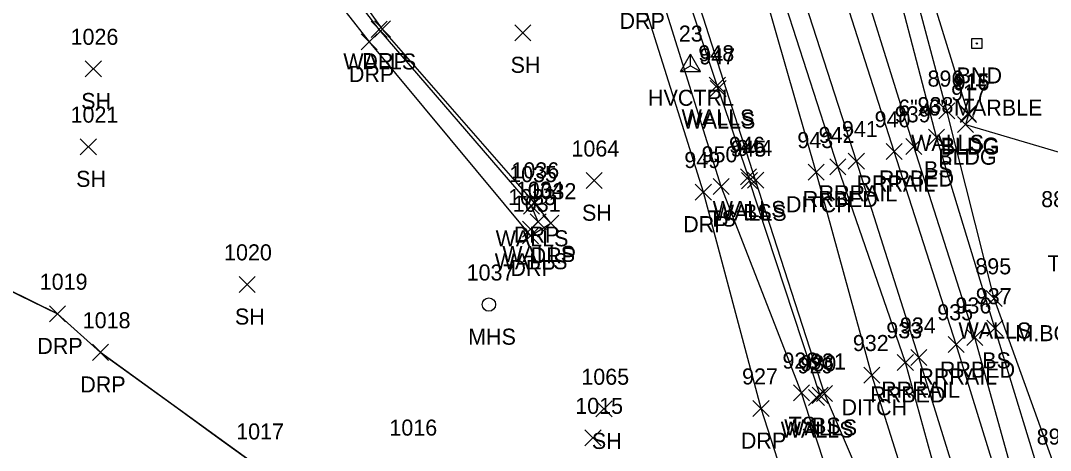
# Model space of a CAD drawing. Extents: x 1462668 to 1465147, y 550359 to 557351.
# Drawn here: x 1464726.3 to 1464854.5, y 552257.6 to 552311.1 of the extents above; entities that cross this region are included whole.
import ezdxf

# ---------------------------------------------------------------- set-up
doc = ezdxf.new("R2010")
doc.units = 0
for name, color, linetype in [('C_A', 7, 'Continuous'), ('C_I', 7, 'Continuous'), ('CPSM', 7, 'Continuous'), ('D_A', 7, 'Continuous'), ('D_I', 7, 'Continuous'), ('D_TIC', 7, 'Continuous'), ('DD', 7, 'Continuous'), ('L_A', 7, 'Continuous'), ('L_C', 7, 'Continuous'), ('L_I', 7, 'Continuous'), ('L_TIC', 7, 'Continuous'), ('LBC', 7, 'Continuous'), ('LELB', 7, 'Continuous'), ('Level 18', 7, 'Continuous'), ('Level 6', 7, 'Continuous'), ('LWS', 7, 'Continuous'), ('M_A', 7, 'Continuous'), ('M_C', 7, 'Continuous'), ('R_A', 7, 'Continuous'), ('R_I', 7, 'Continuous'), ('R_TIC', 7, 'Continuous'), ('RDP', 7, 'Continuous'), ('RR', 7, 'Continuous'), ('RRB', 7, 'Continuous'), ('U_A', 7, 'Continuous'), ('U_I', 7, 'Continuous'), ('USMH', 7, 'Continuous')]:
    doc.layers.add(name, color=color, linetype=linetype)

msp = doc.modelspace()

# ---------------------------------------------------------------- linework, layer by layer
at = {"layer": 'CPSM'}
for p, q in [((1464808.5, 552304.8), (1464809.75, 552306.97)), ((1464811, 552304.8), (1464809.75, 552306.97)), ((1464809.75, 552305.52), (1464809.75, 552306.97)), ((1464808.5, 552304.8), (1464809.75, 552305.52)), ((1464808.5, 552304.8), (1464811, 552304.8)), ((1464809.75, 552305.52), (1464809.75, 552305.52)), ((1464809.75, 552305.52), (1464811, 552304.8))]:
    msp.add_line(p, q, dxfattribs=at)
at = {"layer": 'D_TIC'}
for points in [[(1464824.4, 552291.25), (1464826.4, 552293.25)], [(1464826.4, 552291.25), (1464824.4, 552293.25)], [(1464831.31, 552265.96), (1464833.31, 552267.96)], [(1464833.31, 552265.96), (1464831.31, 552267.96)]]:
    msp.add_lwpolyline(points, dxfattribs=at)
at = {"layer": 'DD'}
msp.add_lwpolyline([(1464838.94, 552245.84), (1464832.31, 552266.96), (1464825.4, 552292.25), (1464817.85, 552318.61), (1464804.29, 552354.78), (1464798.74, 552370.92), (1464794.98, 552381.16)], dxfattribs=at)
at = {"layer": 'L_TIC'}
for points in [[(1464769.98, 552309.05), (1464771.98, 552311.05)], [(1464771.98, 552309.05), (1464769.98, 552311.05)], [(1464787.86, 552308.63), (1464789.86, 552310.63)], [(1464789.86, 552308.63), (1464787.86, 552310.63)], [(1464734.39, 552304.12), (1464736.39, 552306.12)], [(1464736.39, 552304.12), (1464734.39, 552306.12)], [(1464812.08, 552302.07), (1464814.08, 552304.07)], [(1464814.08, 552302.07), (1464812.08, 552304.07)], [(1464812.2, 552301.68), (1464814.2, 552303.68)], [(1464814.2, 552301.68), (1464812.2, 552303.68)], [(1464840.66, 552298.91), (1464842.66, 552300.91)], [(1464842.66, 552298.91), (1464840.66, 552300.91)], [(1464843.3, 552298.56), (1464845.3, 552300.56)], [(1464845.3, 552298.56), (1464843.3, 552300.56)], [(1464843.34, 552298.44), (1464845.34, 552300.44)], [(1464845.34, 552298.44), (1464843.34, 552300.44)], [(1464842.98, 552297.18), (1464844.98, 552299.18)], [(1464844.98, 552297.18), (1464842.98, 552299.18)], [(1464839.37, 552295.61), (1464841.37, 552297.61)], [(1464841.37, 552295.61), (1464839.37, 552297.61)], [(1464733.77, 552294.42), (1464735.77, 552296.42)], [(1464735.77, 552294.42), (1464733.77, 552296.42)], [(1464796.74, 552290.2), (1464798.74, 552292.2)], [(1464798.74, 552290.2), (1464796.74, 552292.2)], [(1464815.96, 552290.66), (1464817.96, 552292.66)], [(1464817.96, 552290.66), (1464815.96, 552292.66)], [(1464816.09, 552290.19), (1464818.09, 552292.19)], [(1464818.09, 552290.19), (1464816.09, 552292.19)], [(1464816.85, 552290.27), (1464818.85, 552292.27)], [(1464818.85, 552290.27), (1464816.85, 552292.27)], [(1464812.57, 552289.48), (1464814.57, 552291.48)], [(1464814.57, 552289.48), (1464812.57, 552291.48)], [(1464788.93, 552287.01), (1464790.93, 552289.01)], [(1464790.93, 552287.01), (1464788.93, 552289.01)], [(1464789.77, 552285.07), (1464791.77, 552287.07)], [(1464791.77, 552285.07), (1464789.77, 552287.07)], [(1464788.82, 552284.15), (1464790.82, 552286.15)], [(1464790.82, 552284.15), (1464788.82, 552286.15)], [(1464753.53, 552277.26), (1464755.53, 552279.26)], [(1464755.53, 552277.26), (1464753.53, 552279.26)], [(1464846.56, 552275.52), (1464848.56, 552277.52)], [(1464848.56, 552275.52), (1464846.56, 552277.52)], [(1464846.62, 552271.8), (1464848.62, 552273.8)], [(1464848.62, 552271.8), (1464846.62, 552273.8)], [(1464822.55, 552263.77), (1464824.55, 552265.77)], [(1464824.55, 552263.77), (1464822.55, 552265.77)], [(1464824.43, 552263.18), (1464826.43, 552265.18)], [(1464826.43, 552263.18), (1464824.43, 552265.18)], [(1464824.87, 552263.44), (1464826.87, 552265.44)], [(1464826.87, 552263.44), (1464824.87, 552265.44)], [(1464825.43, 552263.66), (1464827.43, 552265.66)], [(1464827.43, 552263.66), (1464825.43, 552265.66)], [(1464797.97, 552261.76), (1464799.97, 552263.76)], [(1464799.97, 552261.76), (1464797.97, 552263.76)], [(1464796.6, 552258.13), (1464798.6, 552260.13)], [(1464798.6, 552258.13), (1464796.6, 552260.13)]]:
    msp.add_lwpolyline(points, dxfattribs=at)
at = {"layer": 'LBC'}
for points in [[(1464844.3, 552299.56), (1464837.22, 552322.58)], [(1464844.3, 552299.56), (1464844.34, 552299.44), (1464843.98, 552298.18)], [(1464843.98, 552298.18), (1464858.59, 552293.88)]]:
    msp.add_lwpolyline(points, dxfattribs=at)
at = {"layer": 'LELB'}
for points in [[(1464830.92, 552242.12), (1464823.55, 552264.77), (1464813.57, 552290.48), (1464805.5, 552316.23), (1464797.81, 552336.93), (1464790.24, 552357.62), (1464784.68, 552381.57)], [(1464854.33, 552250.98), (1464847.62, 552272.8), (1464840.37, 552296.61), (1464833.44, 552323.25), (1464825.85, 552341.17), (1464819.51, 552360.06)], [(1464835.15, 552244.31), (1464826.43, 552264.66), (1464817.85, 552291.27), (1464809.14, 552318.34), (1464798.64, 552351.41)]]:
    msp.add_lwpolyline(points, dxfattribs=at)
at = {"layer": 'Level 18'}
msp.add_lwpolyline([(1464844.77, 552308.92), (1464846.02, 552308.92), (1464846.02, 552307.67), (1464844.77, 552307.67)], close=True, dxfattribs=at)
msp.add_circle((1464845.39, 552308.3), 0.0833, dxfattribs=at)
at = {"layer": 'Level 6'}
msp.add_lwpolyline([(1464724.56, 552277.73), (1464730.93, 552274.6), (1464736.28, 552269.8), (1464741.05, 552266.33), (1464745.83, 552262.87), (1464750.61, 552259.4), (1464755.38, 552255.94)], dxfattribs=at)
at = {"layer": 'LWS'}
for points in [[(1464825.43, 552264.18), (1464825.87, 552264.44), (1464817.09, 552291.19), (1464816.96, 552291.66), (1464813.2, 552302.68), (1464813.08, 552303.07), (1464808.69, 552316.22), (1464808.61, 552316.57), (1464805.04, 552327.09), (1464804.87, 552327.61), (1464801.58, 552337.47), (1464801.38, 552337.71), (1464797.67, 552349.15), (1464797.53, 552349.31), (1464794.34, 552358.83), (1464794.22, 552359.09), (1464790.5, 552369.31), (1464790.39, 552369.58), (1464786.94, 552379.64), (1464786.81, 552380.06)], [(1464855.2, 552255.3), (1464847.56, 552276.52), (1464841.66, 552299.91), (1464835.53, 552322.98), (1464835.37, 552323.51), (1464828.08, 552342.62), (1464824.47, 552352.12), (1464816.69, 552371.77), (1464815.76, 552372.82)], [(1464789.82, 552285.15), (1464790.77, 552286.07), (1464789.93, 552288.01), (1464770.98, 552310.05), (1464765.69, 552316.93), (1464765.38, 552317.17), (1464754.16, 552331.73)]]:
    msp.add_lwpolyline(points, dxfattribs=at)
at = {"layer": 'R_TIC'}
for points in [[(1464770.4, 552309.09), (1464772.4, 552311.09)], [(1464772.4, 552309.09), (1464770.4, 552311.09)], [(1464768.72, 552307.48), (1464770.72, 552309.48)], [(1464770.72, 552307.48), (1464768.72, 552309.48)], [(1464834.11, 552293.84), (1464836.11, 552295.84)], [(1464836.11, 552293.84), (1464834.11, 552295.84)], [(1464836.54, 552294.46), (1464838.54, 552296.46)], [(1464838.54, 552294.46), (1464836.54, 552296.46)], [(1464829.39, 552292.62), (1464831.39, 552294.62)], [(1464831.39, 552292.62), (1464829.39, 552294.62)], [(1464827.07, 552291.9), (1464829.07, 552293.9)], [(1464829.07, 552291.9), (1464827.07, 552293.9)], [(1464810.34, 552288.77), (1464812.34, 552290.77)], [(1464812.34, 552288.77), (1464810.34, 552290.77)], [(1464789.26, 552287.48), (1464791.26, 552289.48)], [(1464791.26, 552287.48), (1464789.26, 552289.48)], [(1464791.35, 552284.88), (1464793.35, 552286.88)], [(1464793.35, 552284.88), (1464791.35, 552286.88)], [(1464788.83, 552283.31), (1464790.83, 552285.31)], [(1464790.83, 552283.31), (1464788.83, 552285.31)], [(1464729.93, 552273.6), (1464731.93, 552275.6)], [(1464731.93, 552273.6), (1464729.93, 552275.6)], [(1464844.15, 552270.64), (1464846.15, 552272.64)], [(1464846.15, 552270.64), (1464844.15, 552272.64)], [(1464841.82, 552269.79), (1464843.82, 552271.79)], [(1464843.82, 552269.79), (1464841.82, 552271.79)], [(1464735.28, 552268.8), (1464737.28, 552270.8)], [(1464737.28, 552268.8), (1464735.28, 552270.8)], [(1464837.18, 552268.15), (1464839.18, 552270.15)], [(1464839.18, 552268.15), (1464837.18, 552270.15)], [(1464835.49, 552267.55), (1464837.49, 552269.55)], [(1464837.49, 552267.55), (1464835.49, 552269.55)], [(1464817.52, 552261.8), (1464819.52, 552263.8)], [(1464819.52, 552261.8), (1464817.52, 552263.8)]]:
    msp.add_lwpolyline(points, dxfattribs=at)
at = {"layer": 'RDP'}
for points in [[(1464825.58, 552240.92), (1464818.52, 552262.8), (1464811.34, 552289.77), (1464803.41, 552315.11), (1464795.58, 552336.11), (1464788.93, 552357.1), (1464782.74, 552379.36), (1464782.77, 552383.94)], [(1464752.57, 552330.45), (1464769.72, 552308.48), (1464789.83, 552284.31), (1464792.35, 552285.88), (1464790.26, 552288.48), (1464771.4, 552310.09), (1464766.02, 552317.55), (1464757.16, 552329.54), (1464760.27, 552340.96), (1464763.49, 552351.93)], [(1464765.99, 552228.53), (1464755.38, 552255.94), (1464736.28, 552269.8), (1464730.93, 552274.6), (1464718.19, 552280.87), (1464721.97, 552288.03), (1464702.44, 552298.07)]]:
    msp.add_lwpolyline(points, dxfattribs=at)
at = {"layer": 'RR'}
for points in [[(1464849.39, 552249.53), (1464842.82, 552270.79), (1464835.11, 552294.84), (1464826.26, 552322.52), (1464813.91, 552358.25), (1464808.67, 552373.87), (1464804.99, 552384.75), (1464790.19, 552425.01), (1464777.18, 552458.67), (1464762.36, 552494.61), (1464744.91, 552535.15), (1464735.63, 552555.85), (1464721.29, 552586.6), (1464702.02, 552626.35), (1464686.84, 552656.69), (1464671.35, 552687.14), (1464662.33, 552704.74), (1464642.53, 552744.08), (1464629.16, 552771.13), (1464613.48, 552803.16), (1464601.34, 552828.32)], [(1464844.81, 552247.75), (1464838.18, 552269.15), (1464830.39, 552293.62), (1464821.39, 552321.55), (1464809.52, 552356.64), (1464804.15, 552372.47), (1464800.3, 552383.08), (1464785.6, 552423.21), (1464772.72, 552456.47), (1464757.81, 552492.7), (1464740.23, 552533.39), (1464731.22, 552553.66), (1464716.74, 552584.61), (1464697.67, 552624.11), (1464682.45, 552654.5), (1464666.88, 552684.94), (1464657.73, 552702.87), (1464638.13, 552741.98), (1464624.71, 552769), (1464609.23, 552800.97), (1464596.7, 552826.14)]]:
    msp.add_lwpolyline(points, dxfattribs=at)
at = {"layer": 'RRB'}
for points in [[(1464851.04, 552250.44), (1464845.15, 552271.64), (1464837.54, 552295.46), (1464828.77, 552323.58), (1464816.78, 552359.11), (1464810.93, 552374.77), (1464807.84, 552386.03), (1464792.77, 552426.04), (1464778.94, 552461.75), (1464771.17, 552477.61), (1464764.62, 552495.61), (1464747.04, 552536.3), (1464737.62, 552557.17), (1464723.44, 552587.94), (1464704.53, 552627.92), (1464689.19, 552657.62), (1464673.57, 552688.33), (1464664.01, 552705.15), (1464644.5, 552745.11), (1464631.56, 552772.37), (1464615.64, 552804.18), (1464603.91, 552829.42)], [(1464842.44, 552246.93), (1464836.49, 552268.55), (1464828.07, 552292.9), (1464819.09, 552320.89), (1464807.29, 552355.87), (1464801.46, 552371.53), (1464797.6, 552381.72), (1464783.01, 552422.47), (1464769.41, 552454.58), (1464755.32, 552491.81), (1464738.61, 552532.38), (1464729.39, 552552.76), (1464715, 552583.84), (1464695.07, 552622.98), (1464679.55, 552653), (1464663.95, 552683.28), (1464654.86, 552701.9), (1464635.34, 552740.46), (1464622.38, 552767.72), (1464607.07, 552799.75), (1464594.74, 552825)]]:
    msp.add_lwpolyline(points, dxfattribs=at)
at = {"layer": 'USMH'}
for p, q in [((1464784.64, 552275.75), (1464784.64, 552275.75)), ((1464785.48, 552275.75), (1464785.48, 552275.75))]:
    msp.add_line(p, q, dxfattribs=at)
msp.add_circle((1464784.64, 552275.75), 0.833, dxfattribs=at)

# ---------------------------------------------------------------- texts
at = {"layer": 'C_A'}
msp.add_text('HVCTRL', height=2, dxfattribs=at).set_placement((1464804.45, 552300.52))
at = {"layer": 'C_I'}
msp.add_text('23', height=2, dxfattribs=at).set_placement((1464808.29, 552308.52))
at = {"layer": 'D_A'}
for p in [(1464821.63, 552287.25), (1464828.54, 552261.96)]:
    msp.add_text('DITCH', height=2, dxfattribs=at).set_placement(p)
at = {"layer": 'D_I'}
for s, p in [('943', (1464823.04, 552295.25)), ('932', (1464829.95, 552269.96))]:
    msp.add_text(s, height=2, dxfattribs=at).set_placement(p)
at = {"layer": 'L_A'}
for s, p in [('WALLS', (1464766.52, 552305.05)), ('SH', (1464787.34, 552304.63)), ('SH', (1464733.88, 552300.12)), ('WALLS', (1464808.63, 552298.07)), ('WALLS', (1464808.74, 552297.68)), ('WALLS', (1464837.21, 552294.91)), ('BLDG', (1464840.89, 552294.56)), ('BLDG', (1464840.93, 552294.44)), ('BLDG', (1464840.57, 552293.18)), ('BS', (1464838.81, 552291.61)), ('SH', (1464733.25, 552290.42)), ('SH', (1464796.23, 552286.2)), ('WALLS', (1464812.5, 552286.66)), ('WALLS', (1464812.64, 552286.19)), ('BS', (1464816.29, 552286.27)), ('TS', (1464811.98, 552285.48)), ('WALLS', (1464785.48, 552283.01)), ('WALLS', (1464786.31, 552281.07)), ('WALLS', (1464785.36, 552280.15)), ('TS', (1464854.18, 552279.89)), ('SH', (1464753.02, 552273.26)), ('WALLS', (1464843.1, 552271.52)), ('BS', (1464846.06, 552267.8)), ('WALLS', (1464820.97, 552259.18)), ('WALLS', (1464821.41, 552259.44)), ('TS', (1464821.96, 552259.77)), ('BS', (1464824.87, 552259.66)), ('SH', (1464797.46, 552257.76))]:
    msp.add_text(s, height=2, dxfattribs=at).set_placement(p)
at = {"layer": 'L_C'}
msp.add_text('M.BOXELDER', height=2, dxfattribs=at).set_placement((1464850.19, 552271.19))
at = {"layer": 'L_I'}
for s, p in [('1026', (1464732.56, 552308.12)), ('948', (1464810.72, 552306.07)), ('947', (1464810.84, 552305.68)), ('896', (1464839.25, 552302.91)), ('916', (1464842.49, 552302.44)), ('915', (1464842.5, 552302.56)), ('917', (1464842.19, 552301.18)), ('938', (1464838.01, 552299.61)), ('1021', (1464732.56, 552298.42)), ('1064', (1464794.92, 552294.2)), ('946', (1464814.54, 552294.66)), ('945', (1464814.73, 552294.19)), ('944', (1464815.48, 552294.27)), ('950', (1464811.12, 552293.48)), ('1035', (1464787.16, 552291.01)), ('1034', (1464788, 552289.07)), ('1033', (1464787.04, 552288.15)), ('889', (1464853.4, 552287.89)), ('1020', (1464751.67, 552281.26)), ('895', (1464845.2, 552279.52)), ('937', (1464845.26, 552275.8)), ('928', (1464821.19, 552267.77)), ('929', (1464823.06, 552267.18)), ('930', (1464823.42, 552267.44)), ('931', (1464824.63, 552267.66)), ('1065', (1464796.15, 552265.76)), ('1015', (1464795.39, 552262.13)), ('1016', (1464772.25, 552259.42)), ('894', (1464852.84, 552258.3))]:
    msp.add_text(s, height=2, dxfattribs=at).set_placement(p)
at = {"layer": 'M_A'}
msp.add_text('BND', height=2, dxfattribs=at).set_placement((1464842.88, 552303.3))
at = {"layer": 'M_C'}
msp.add_text('6"x6" MARBLE', height=2, dxfattribs=at).set_placement((1464835.6, 552299.3))
at = {"layer": 'R_A'}
for s, p in [('DRP', (1464800.9, 552310.11)), ('DRP', (1464768.89, 552305.09)), ('DRP', (1464767.21, 552303.48)), ('RRRAIL', (1464830.4, 552289.84)), ('RRBED', (1464833.19, 552290.46)), ('RRRAIL', (1464825.68, 552288.62)), ('RRBED', (1464823.71, 552287.9)), ('DRP', (1464808.83, 552284.77)), ('DRP', (1464787.75, 552283.48)), ('DRP', (1464789.84, 552280.88)), ('DRP', (1464787.32, 552279.31)), ('DRP', (1464728.42, 552269.6)), ('RRRAIL', (1464838.11, 552265.79)), ('RRBED', (1464840.79, 552266.64)), ('DRP', (1464733.77, 552264.8)), ('RRBED', (1464832.13, 552263.55)), ('RRRAIL', (1464833.47, 552264.15)), ('DRP', (1464816.01, 552257.8))]:
    msp.add_text(s, height=2, dxfattribs=at).set_placement(p)
at = {"layer": 'R_I'}
for s, p in [('940', (1464832.66, 552297.84)), ('939', (1464835.17, 552298.46)), ('941', (1464828.59, 552296.62)), ('942', (1464825.7, 552295.9)), ('949', (1464808.97, 552292.77)), ('1036', (1464787.44, 552291.48)), ('1032', (1464789.58, 552288.88)), ('1031', (1464787.62, 552287.31)), ('1019', (1464728.72, 552277.6)), ('936', (1464842.73, 552274.64)), ('935', (1464840.46, 552273.79)), ('1018', (1464734.07, 552272.8)), ('934', (1464835.81, 552272.15)), ('933', (1464834.12, 552271.55)), ('927', (1464816.16, 552265.8)), ('1017', (1464753.18, 552258.94))]:
    msp.add_text(s, height=2, dxfattribs=at).set_placement(p)
at = {"layer": 'U_A'}
msp.add_text('MHS', height=2, dxfattribs=at).set_placement((1464782.06, 552270.75))
at = {"layer": 'U_I'}
msp.add_text('1037', height=2, dxfattribs=at).set_placement((1464781.87, 552278.75))

doc.saveas('drawing.dxf')
